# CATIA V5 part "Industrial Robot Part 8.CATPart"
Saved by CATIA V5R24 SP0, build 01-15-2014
Part number: Industrial Robot Part 8
Source: Unknown
Material "Bright Orange": density 7860 kg/m3, Young's modulus 2e+11 Pa, Poisson ratio 0.266
Bounding box of the stored display mesh (mm): x 1720.669 to 2061.104, y -155.998 to 144.002, z 1460.115 to 1620.115
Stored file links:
  C:\Users\cdl\Downloads\2024_CAD_final\p2\Industrial Robot Part 8.CATPart
  D:\Program Files\Dassault Systemes\B24\win_b64\startup\materials\Catalog.CATMaterial
  D:\Lectures\Catia DMU Lecture Notes\2부 Practice Files\Industrial Robot PickUp Simulation\Result\Industrial Robot PickUp.CATProduct
  D:\Lectures\Catia DMU Lecture Notes\2부 Practice Files\Industrial Robot PickUp Simulation\Result\Path Layout.CATPart
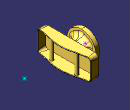
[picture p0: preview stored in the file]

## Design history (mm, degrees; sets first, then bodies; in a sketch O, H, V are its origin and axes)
Set1 "Moving Point"
  Point1: type OnCurve, Support {line type PtPt, FirstPoint {point type OnCurve, Support DatumCurve1, Ratio 0.5}, SecondPoint {point type OnCurve, Support DatumCurve2, Ratio 0.5}}, Ratio 0.5
  DatumCurve1
  DatumCurve2
  Point2: type Center, Curve edge [face of Solid1 | face of Solid1]
  Line1: type PtDir, RefPoint Point1, Direction face of Solid1, Start -578, End 0
Body1 (main body), material "Bright Orange"
  Solid1 "Solid 1": solid without history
